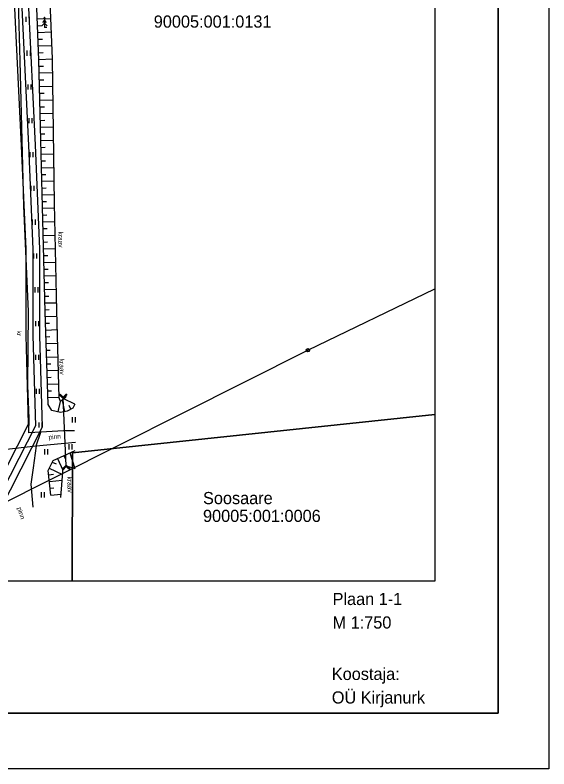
# Model space of a CAD drawing. Extents: x 657488 to 657645, y 6569018 to 6569240.
# Drawn here: x 657566.5 to 657645.4, y 6569017.6 to 6569129 of the extents above; entities that cross this region are included whole.
import ezdxf

# ---------------------------------------------------------------- set-up
doc = ezdxf.new("R2010")
doc.units = 0
for name, color, linetype in [('HALJASTUS', 7, 'Continuous'), ('KASUTUSALA', 7, 'Continuous'), ('MPOHULIIN', 7, 'Continuous'), ('OL_SIDE', 7, 'Continuous'), ('PIIR', 7, 'Continuous'), ('POST', 7, 'Continuous'), ('PR_SIDE', 7, 'Continuous'), ('PUU', 7, 'Continuous'), ('RELJEEF', 7, 'Continuous'), ('TEE', 7, 'Continuous'), ('TRUUP', 7, 'Continuous'), ('VEEKOGU', 7, 'Continuous'), ('VORMISTUS', 7, 'Continuous')]:
    doc.layers.add(name, color=color, linetype=linetype)

msp = doc.modelspace()

# ---------------------------------------------------------------- linework, layer by layer
at = {"layer": 'HALJASTUS'}
for p, q in [((657568.13, 6569128.78), (657568.13, 6569128.02)), ((657568.59, 6569128.78), (657568.59, 6569128.02)), ((657568.27, 6569123.79), (657568.27, 6569123.03)), ((657568.73, 6569123.79), (657568.73, 6569123.03)), ((657568.42, 6569118.79), (657568.42, 6569118.03)), ((657568.87, 6569118.79), (657568.87, 6569118.03)), ((657568.56, 6569113.79), (657568.56, 6569113.03)), ((657569.02, 6569113.79), (657569.02, 6569113.03)), ((657568.71, 6569108.79), (657568.71, 6569108.03)), ((657569.16, 6569108.79), (657569.16, 6569108.03)), ((657568.85, 6569103.79), (657568.85, 6569103.03)), ((657569.31, 6569103.79), (657569.31, 6569103.03)), ((657569.03, 6569098.8), (657569.03, 6569098.04)), ((657569.49, 6569098.8), (657569.49, 6569098.04)), ((657569.23, 6569093.8), (657569.23, 6569093.04)), ((657569.69, 6569093.8), (657569.69, 6569093.04)), ((657569.44, 6569088.81), (657569.44, 6569088.04)), ((657569.89, 6569088.81), (657569.89, 6569088.04)), ((657569.55, 6569083.81), (657569.55, 6569083.05)), ((657570, 6569083.81), (657570, 6569083.05)), ((657569.55, 6569078.81), (657569.55, 6569078.05)), ((657570, 6569078.81), (657570, 6569078.05)), ((657569.63, 6569073.81), (657569.63, 6569073.05)), ((657570.08, 6569073.81), (657570.08, 6569073.05)), ((657574.95, 6569069.59), (657574.95, 6569068.83)), ((657575.41, 6569069.59), (657575.41, 6569068.83)), ((657570.01, 6569068.83), (657570.01, 6569068.07)), ((657570.46, 6569068.83), (657570.46, 6569068.07)), ((657574.45, 6569065.59), (657574.45, 6569064.82)), ((657574.9, 6569065.59), (657574.9, 6569064.82)), ((657570.87, 6569064.86), (657570.87, 6569064.1)), ((657571.32, 6569064.86), (657571.32, 6569064.1)), ((657570.37, 6569058.5), (657570.37, 6569057.74)), ((657570.83, 6569058.5), (657570.83, 6569057.74))]:
    msp.add_line(p, q, dxfattribs=at)
at = {"layer": 'KASUTUSALA'}
msp.add_lwpolyline([(657568.45, 6569131.11), (657569.49, 6569109.78), (657570.15, 6569094.47), (657570.15, 6569081.68), (657570.54, 6569068.12), (657564.19, 6569055.71), (657563.73, 6569054.82), (657561.95, 6569055.74), (657568.52, 6569068.57), (657568.15, 6569081.65), (657568.15, 6569094.43), (657567.49, 6569109.69), (657566.45, 6569131.06)], dxfattribs=at)
at = {"layer": 'MPOHULIIN'}
msp.add_lwpolyline([(657541.39, 6569045.36), (657563.28, 6569056.16), (657609.81, 6569079.49), (657628.56, 6569088.56)], dxfattribs=at)
at = {"layer": 'OL_SIDE'}
msp.add_lwpolyline([(657563.28, 6569056.16), (657609.81, 6569079.49), (657628.56, 6569088.56)], dxfattribs=at)
at = {"layer": 'PIIR'}
for points in [[(657574.94, 6569045.36), (657575.02, 6569064.35), (657628.56, 6569070.01)], [(657628.56, 6569070.01), (657575.02, 6569064.35), (657574.94, 6569045.36)]]:
    msp.add_lwpolyline(points, dxfattribs=at)
at = {"layer": 'POST'}
for radius in [0.25, 0.0234]:
    msp.add_circle((657609.81, 6569079.49), radius, dxfattribs=at)
at = {"layer": 'PR_SIDE'}
msp.add_lwpolyline([(657567.09, 6569181.05), (657567.01, 6569180.84), (657566.79, 6569176.4), (657567, 6569171.4), (657567, 6569165.54), (657567, 6569158.58), (657567, 6569151.02), (657567.45, 6569143.71), (657567.45, 6569137.24), (657567.45, 6569131.08), (657568.49, 6569109.73), (657569.15, 6569094.45), (657569.15, 6569081.66), (657569.53, 6569068.34), (657563.3, 6569056.17)], dxfattribs=at)
at = {"layer": 'PUU'}
for p, q in [((657570.87, 6569128.7), (657570.72, 6569128.45)), ((657571.02, 6569128.45), (657570.87, 6569128.7)), ((657570.87, 6569128.7), (657570.87, 6569127.2)), ((657570.87, 6569127.85), (657570.47, 6569127.45)), ((657570.87, 6569128.3), (657570.57, 6569127.95)), ((657571.17, 6569127.95), (657570.87, 6569128.3)), ((657571.27, 6569127.45), (657570.87, 6569127.85)), ((657571.23, 6569127.2), (657570.87, 6569127.2))]:
    msp.add_line(p, q, dxfattribs=at)
at = {"layer": 'RELJEEF'}
for p, q in [((657569.8, 6569128.46), (657571.8, 6569128.54)), ((657569.84, 6569127.46), (657570.51, 6569127.49)), ((657569.88, 6569126.46), (657571.88, 6569126.54)), ((657569.92, 6569125.46), (657570.59, 6569125.49)), ((657569.96, 6569124.47), (657571.96, 6569124.54)), ((657570, 6569123.47), (657570.67, 6569123.49)), ((657570.04, 6569122.47), (657572.04, 6569122.55)), ((657570.06, 6569121.47), (657570.73, 6569121.48)), ((657570.09, 6569120.47), (657572.07, 6569120.52)), ((657570.11, 6569119.47), (657570.77, 6569119.48)), ((657570.14, 6569118.47), (657572.1, 6569118.52)), ((657570.16, 6569117.47), (657570.81, 6569117.48)), ((657570.18, 6569116.47), (657572.13, 6569116.52)), ((657570.21, 6569115.47), (657570.85, 6569115.48)), ((657570.23, 6569114.47), (657572.16, 6569114.52)), ((657570.26, 6569113.47), (657570.9, 6569113.49)), ((657570.28, 6569112.47), (657572.19, 6569112.52)), ((657570.3, 6569111.47), (657570.94, 6569111.49)), ((657570.33, 6569110.47), (657572.22, 6569110.52)), ((657570.35, 6569109.47), (657570.98, 6569109.49)), ((657570.38, 6569108.47), (657572.25, 6569108.52)), ((657570.4, 6569107.47), (657571.02, 6569107.49)), ((657570.43, 6569106.47), (657572.28, 6569106.52)), ((657570.45, 6569105.47), (657571.07, 6569105.49)), ((657570.47, 6569104.47), (657572.31, 6569104.52)), ((657570.5, 6569103.47), (657571.11, 6569103.49)), ((657570.52, 6569102.47), (657572.34, 6569102.52)), ((657570.55, 6569101.47), (657571.15, 6569101.49)), ((657570.57, 6569100.47), (657572.38, 6569100.52)), ((657570.6, 6569099.47), (657571.2, 6569099.49)), ((657570.62, 6569098.47), (657572.42, 6569098.52)), ((657570.65, 6569097.47), (657571.25, 6569097.49)), ((657570.68, 6569096.47), (657572.46, 6569096.52)), ((657570.7, 6569095.48), (657571.3, 6569095.49)), ((657570.73, 6569094.48), (657572.5, 6569094.52)), ((657570.76, 6569093.48), (657571.34, 6569093.49)), ((657570.78, 6569092.48), (657572.54, 6569092.52)), ((657570.81, 6569091.48), (657571.39, 6569091.49)), ((657570.84, 6569090.48), (657572.58, 6569090.52)), ((657570.86, 6569089.48), (657571.44, 6569089.49)), ((657570.89, 6569088.48), (657572.62, 6569088.52)), ((657570.92, 6569087.48), (657571.49, 6569087.49)), ((657570.94, 6569086.48), (657572.66, 6569086.52)), ((657570.97, 6569085.48), (657571.54, 6569085.49)), ((657571, 6569084.48), (657572.7, 6569084.54)), ((657571.03, 6569083.48), (657571.6, 6569083.5)), ((657571.07, 6569082.48), (657572.76, 6569082.54)), ((657571.1, 6569081.48), (657571.66, 6569081.5)), ((657571.13, 6569080.48), (657572.81, 6569080.54)), ((657571.16, 6569079.48), (657571.72, 6569079.5)), ((657571.2, 6569078.48), (657572.87, 6569078.54)), ((657571.23, 6569077.48), (657571.79, 6569077.5)), ((657571.26, 6569076.48), (657572.93, 6569076.54)), ((657571.3, 6569075.48), (657571.85, 6569075.5)), ((657571.33, 6569074.48), (657572.98, 6569074.54)), ((657571.36, 6569073.49), (657571.91, 6569073.5)), ((657571.4, 6569072.49), (657573.04, 6569072.54)), ((657572.88, 6569070.37), (657573.23, 6569071.89)), ((657573.86, 6569070.41), (657573.51, 6569072.12)), ((657575.36, 6569071.54), (657573.75, 6569072.31)), ((657572.88, 6569070.37), (657573, 6569070.88)), ((657574.78, 6569070.78), (657574.5, 6569071.34)), ((657574.61, 6569064.33), (657575.34, 6569062.01)), ((657572.01, 6569062.95), (657572.57, 6569062.68)), ((657572.8, 6569063.49), (657573.58, 6569061.78)), ((657573.71, 6569063.91), (657573.95, 6569063.37)), ((657571.58, 6569062.04), (657573.53, 6569061.12)), ((657571.5, 6569061.08), (657572.18, 6569061.15)), ((657571.59, 6569060.08), (657573.46, 6569060.27)), ((657571.69, 6569059.09), (657572.26, 6569059.14)), ((657571.79, 6569058.09), (657573.3, 6569058.24))]:
    msp.add_line(p, q, dxfattribs=at)
for points in [[(657575.36, 6569071.54), (657575.06, 6569070.92), (657574.2, 6569070.48), (657573.25, 6569070.29), (657571.97, 6569070.57), (657571.43, 6569071.46), (657570.98, 6569085.15), (657570.57, 6569100.67), (657570.04, 6569122.39), (657569.28, 6569141.75), (657568.88, 6569162.5), (657567.5, 6569180.05), (657567.7, 6569183.91), (657568.88, 6569185.76), (657571.05, 6569186.4), (657579.98, 6569184.56), (657590.65, 6569182), (657604.79, 6569180.59)], [(657571.79, 6569058.09), (657571.43, 6569061.73), (657572.13, 6569063.18), (657575.39, 6569064.68)]]:
    msp.add_lwpolyline(points, dxfattribs=at)
at = {"layer": 'TEE'}
msp.add_line((657569.62, 6569065.37), (657575.45, 6569065.89), dxfattribs=at)
for points in [[(657554.4, 6569062), (657559.25, 6569063.03), (657564.82, 6569064.83), (657569.62, 6569065.37), (657570.35, 6569067.36), (657568.53, 6569067.26), (657568.59, 6569069.38), (657568.42, 6569074.3), (657568.5, 6569085.24), (657567.81, 6569100.86), (657567.28, 6569122.21), (657566.73, 6569141.77), (657566.17, 6569162.21), (657566.11, 6569180.12), (657566.26, 6569183.44), (657568.59, 6569186.68), (657570.88, 6569187.83)], [(657575.32, 6569067.57), (657573.66, 6569067.57), (657570.35, 6569067.36)], [(657569.62, 6569065.37), (657569.18, 6569062.13), (657568.86, 6569059.71), (657569.14, 6569056.31)]]:
    msp.add_lwpolyline(points, dxfattribs=at)
at = {"layer": 'TRUUP'}
for p, q in [((657573.17, 6569072.98), (657573.07, 6569072.88)), ((657573.07, 6569072.88), (657573.65, 6569072.35)), ((657573.09, 6569072.9), (657573.12, 6569072.84)), ((657573.11, 6569072.92), (657573.16, 6569072.8)), ((657573.12, 6569072.93), (657573.64, 6569072.45)), ((657573.13, 6569072.94), (657573.2, 6569072.76)), ((657573.15, 6569072.96), (657573.24, 6569072.72)), ((657573.17, 6569072.98), (657573.64, 6569072.55)), ((657573.17, 6569072.98), (657573.28, 6569072.69)), ((657573.21, 6569072.94), (657573.32, 6569072.65)), ((657573.25, 6569072.91), (657573.36, 6569072.61)), ((657573.29, 6569072.87), (657573.4, 6569072.57)), ((657573.64, 6569072.55), (657574.07, 6569073.02)), ((657573.64, 6569072.45), (657574.12, 6569072.97)), ((657573.65, 6569072.35), (657574.17, 6569072.92)), ((657573.93, 6569072.87), (657573.99, 6569072.72)), ((657573.95, 6569072.89), (657574.01, 6569072.74)), ((657573.97, 6569072.91), (657574.03, 6569072.76)), ((657573.99, 6569072.93), (657574.05, 6569072.78)), ((657574.01, 6569072.95), (657574.06, 6569072.8)), ((657574.03, 6569072.97), (657574.08, 6569072.82)), ((657574.05, 6569072.99), (657574.1, 6569072.84)), ((657574.06, 6569073.01), (657574.12, 6569072.87)), ((657574.07, 6569073.02), (657574.17, 6569072.92)), ((657574.1, 6569072.99), (657574.14, 6569072.89)), ((657574.14, 6569072.95), (657574.16, 6569072.91)), ((657573.33, 6569072.83), (657573.44, 6569072.54)), ((657573.37, 6569072.79), (657573.49, 6569072.5)), ((657573.41, 6569072.76), (657573.53, 6569072.46)), ((657573.46, 6569072.72), (657573.57, 6569072.42)), ((657573.5, 6569072.68), (657573.61, 6569072.39)), ((657573.54, 6569072.64), (657573.65, 6569072.35)), ((657573.58, 6569072.61), (657573.67, 6569072.37)), ((657573.62, 6569072.57), (657573.69, 6569072.39)), ((657574.07, 6569062.4), (657573.64, 6569072.45)), ((657573.65, 6569072.56), (657573.7, 6569072.41)), ((657573.67, 6569072.58), (657573.72, 6569072.43)), ((657573.69, 6569072.6), (657573.74, 6569072.45)), ((657573.71, 6569072.62), (657573.76, 6569072.47)), ((657573.72, 6569072.64), (657573.78, 6569072.49)), ((657573.74, 6569072.66), (657573.8, 6569072.52)), ((657573.76, 6569072.68), (657573.82, 6569072.54)), ((657573.78, 6569072.71), (657573.84, 6569072.56)), ((657573.8, 6569072.73), (657573.86, 6569072.58)), ((657573.82, 6569072.75), (657573.88, 6569072.6)), ((657573.84, 6569072.77), (657573.89, 6569072.62)), ((657573.86, 6569072.79), (657573.91, 6569072.64)), ((657573.88, 6569072.81), (657573.93, 6569072.66)), ((657573.89, 6569072.83), (657573.95, 6569072.68)), ((657573.91, 6569072.85), (657573.97, 6569072.7)), ((657574.07, 6569062.5), (657573.54, 6569061.93)), ((657573.64, 6569061.83), (657573.54, 6569061.93)), ((657573.57, 6569061.9), (657573.55, 6569061.95)), ((657573.61, 6569061.86), (657573.57, 6569061.97)), ((657574.07, 6569062.4), (657573.59, 6569061.88)), ((657573.65, 6569061.84), (657573.59, 6569061.99)), ((657573.67, 6569061.86), (657573.61, 6569062.01)), ((657573.69, 6569061.88), (657573.63, 6569062.03)), ((657574.07, 6569062.3), (657573.64, 6569061.83)), ((657573.7, 6569061.9), (657573.65, 6569062.05)), ((657573.72, 6569061.92), (657573.67, 6569062.07)), ((657573.74, 6569061.94), (657573.69, 6569062.09)), ((657573.76, 6569061.96), (657573.71, 6569062.11)), ((657573.78, 6569061.98), (657573.72, 6569062.13)), ((657573.8, 6569062), (657573.74, 6569062.15)), ((657573.82, 6569062.02), (657573.76, 6569062.17)), ((657573.84, 6569062.04), (657573.78, 6569062.19)), ((657573.86, 6569062.06), (657573.8, 6569062.21)), ((657573.88, 6569062.09), (657573.82, 6569062.23)), ((657573.89, 6569062.11), (657573.84, 6569062.26)), ((657573.91, 6569062.13), (657573.86, 6569062.28)), ((657573.93, 6569062.15), (657573.88, 6569062.3)), ((657573.95, 6569062.17), (657573.89, 6569062.32)), ((657573.97, 6569062.19), (657573.91, 6569062.34)), ((657573.99, 6569062.21), (657573.93, 6569062.36)), ((657574.01, 6569062.23), (657573.95, 6569062.38)), ((657574.03, 6569062.25), (657573.97, 6569062.4)), ((657574.05, 6569062.27), (657573.99, 6569062.42)), ((657574.06, 6569062.29), (657574.01, 6569062.44)), ((657574.09, 6569062.28), (657574.03, 6569062.46)), ((657574.14, 6569062.25), (657574.05, 6569062.48)), ((657574.64, 6569061.98), (657574.07, 6569062.5)), ((657574.18, 6569062.21), (657574.07, 6569062.5)), ((657574.59, 6569061.92), (657574.07, 6569062.4)), ((657574.54, 6569061.87), (657574.07, 6569062.3)), ((657574.22, 6569062.17), (657574.11, 6569062.47)), ((657574.26, 6569062.13), (657574.15, 6569062.43)), ((657574.3, 6569062.1), (657574.19, 6569062.39)), ((657574.34, 6569062.06), (657574.23, 6569062.35)), ((657574.38, 6569062.02), (657574.27, 6569062.32)), ((657574.42, 6569061.98), (657574.31, 6569062.28)), ((657574.46, 6569061.95), (657574.35, 6569062.24)), ((657574.5, 6569061.91), (657574.39, 6569062.2)), ((657574.54, 6569061.87), (657574.43, 6569062.17)), ((657574.56, 6569061.89), (657574.47, 6569062.13)), ((657574.58, 6569061.91), (657574.51, 6569062.09)), ((657574.54, 6569061.87), (657574.64, 6569061.98)), ((657574.6, 6569061.93), (657574.56, 6569062.05)), ((657574.62, 6569061.96), (657574.6, 6569062.02))]:
    msp.add_line(p, q, dxfattribs=at)
at = {"layer": 'VEEKOGU'}
for points in [[(657574.07, 6569073.06), (657573.98, 6569072.5), (657573.23, 6569071.89), (657573.04, 6569072.48), (657572.68, 6569085.31), (657572.36, 6569101.18), (657572.04, 6569122.58), (657571.25, 6569141.93), (657570.11, 6569162.81), (657570.01, 6569179.62), (657570.44, 6569183.34), (657571.04, 6569183.41), (657571.78, 6569182.92), (657571.76, 6569181.99), (657571.43, 6569179.61), (657571.43, 6569175.99)], [(657573.26, 6569057.74), (657573.61, 6569062.12), (657574.07, 6569062.4), (657575.34, 6569062.01)]]:
    msp.add_lwpolyline(points, dxfattribs=at)
at = {"layer": 'VORMISTUS'}
for points in [[(657487.94, 6569240.36), (657645.44, 6569240.36), (657645.44, 6569017.61), (657487.94, 6569017.61)], [(657495.44, 6569025.86), (657637.94, 6569025.86), (657637.94, 6569232.11), (657495.44, 6569232.11)], [(657495.44, 6569232.11), (657637.94, 6569232.11), (657637.94, 6569025.86), (657495.44, 6569025.86)], [(657628.56, 6569045.36), (657504.81, 6569045.36), (657504.81, 6569202.86), (657628.56, 6569202.86)]]:
    msp.add_lwpolyline(points, close=True, dxfattribs=at)

# ---------------------------------------------------------------- texts
at = {"layer": 'PIIR'}
for s, p in [('90005:001:0131', (657587.02, 6569127.17)), ('Soosaare', (657594.3, 6569056.74)), ('90005:001:0006', (657594.3, 6569054.11))]:
    msp.add_text(s, height=1.8, dxfattribs=at).set_placement(p)
at = {"layer": 'TEE'}
for s, rotation, p in [('kr', 269.9544, (657566.78, 6569082.37)), ('pinn', 5.8033, (657571.49, 6569066.28)), ('pinn', 288.1182, (657566.8, 6569056.17))]:
    msp.add_text(s, height=0.7, rotation=rotation, dxfattribs=at).set_placement(p)
at = {"layer": 'VEEKOGU'}
for p in [(657572.9, 6569097.03), (657573.07, 6569078.23), (657574.24, 6569060.8)]:
    msp.add_text('kraav', height=0.7, rotation=271.096, dxfattribs=at).set_placement(p)
at = {"layer": 'VORMISTUS'}
for s, p in [('Plaan 1-1', (657613.45, 6569041.83)), ('M 1:750', (657613.45, 6569038.35)), ('Koostaja:', (657613.34, 6569030.75)), ('OÜ Kirjanurk', (657613.34, 6569027.27))]:
    msp.add_text(s, height=1.8, dxfattribs=at).set_placement(p)

doc.saveas('drawing.dxf')
